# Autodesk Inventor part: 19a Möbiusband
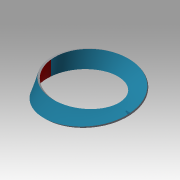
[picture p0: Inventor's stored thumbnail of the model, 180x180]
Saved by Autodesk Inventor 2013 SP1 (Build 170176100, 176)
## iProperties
Created: 2012-10
Part Number: 19a Möbiusband
Material: Allgemein
Document SubType Name: Modeling
Designer: Administrator
Density: 1 g/cm^3
Mass: 125.623 g
Surface Area: 568.268 cm^2
Volume: 125.623 cm^3
Author: Administrator
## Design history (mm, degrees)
sketch "3D-Skizze1"
  node "3D-Gleichungskurve1" dims "d0" = 0, "d1" = 1800
sketch "3D-Skizze2"
  node "3D-Gleichungskurve2" dims "d2" = 0, "d3" = 1800
node "Mittelachse"
  node "3D-Gleichungskurve3" dims "d17" = 0, "d18" = 3600
workplane "Arbeitsebene31"
sketch "Skizze6"
  geometry: L1 (20, -2.5)-(-20, -2.5); L2 (-20, -2.5)-(-20, 2.5); L3 (-20, 2.5)-(20, 2.5); L4 (20, 2.5)-(20, -2.5); L5 (20, -2.5)-(-20, 2.5); L6 (-20, -2.5)-(20, 2.5); 3 further points
  constraints: 12 end point, 3 midpoint, 2 parallel, 1 horizontal, 1 perpendicular
  dimensions: "d29" = 5 distance between parallel lines of L1 L3
feature "Sweeping2" sketch "Skizze6" dims "d31" = 0
sketch "3D-Skizze9"
sketch "3D-Skizze10"
sketch "Skizze7"
  geometry: 6 further points
  constraints: 3 horizontal alignment, 2 vertical alignment
feature "Sweeping3" sketch "3D-Skizze9", "3D-Skizze10", "Skizze7" dims "d36" = 0
node "Volumenkörper2"
node "3D-Gleichungskurve5" dims "d32" = 1800, "d33" = 3600
node "3D-Gleichungskurve6" dims "d34" = 1800, "d35" = 3600
